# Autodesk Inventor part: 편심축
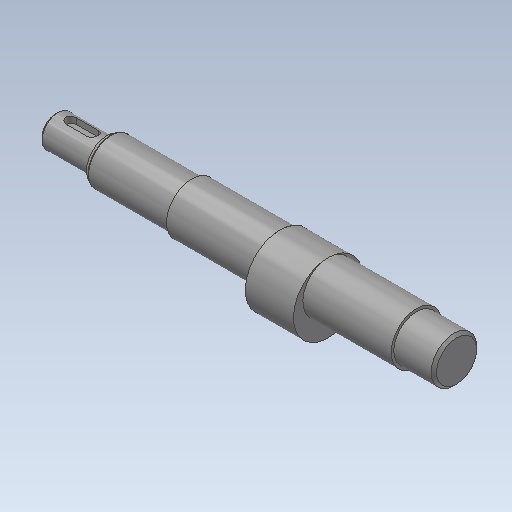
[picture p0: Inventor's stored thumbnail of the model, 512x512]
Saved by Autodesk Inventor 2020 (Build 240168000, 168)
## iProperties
Created: 2017-08
Part Number: 편심축
Material: 강철, 연강
Document SubType Name: Modeling
Designer: mduedu
Density: 1 g/cm^3
Appearance: 강철
Author: mduedu
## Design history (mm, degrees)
sketch "스케치1"
  geometry: L1 (0, 0)-(150, 0); L2 (150, 0)-(150, 8.5); L3 (150, 8.5)-(135, 8.5); L4 (135, 8.5)-(135, 9.5); L5 (135, 9.5)-(51, 9.5); L6 (51, 9.5)-(51, 8.5); L7 (51, 8.5)-(19, 8.5); L8 (19, 8.5)-(19, 6); L9 (19, 6)-(0, 6); L10 (0, 6)-(0, 0)
  constraints: 20 end point, 6 parallel, 2 collinear, 2 perpendicular, 1 horizontal
  dimensions: "d0" = 150 distance of L1.start L1.end; "d1" = 17 diameter of L3 L1; "d2" = 19 diameter of L5 L1; "d3" = 12 diameter of L9 L1; "d4" = 19 distance of L8.end L9.end; "d5" = 15 distance of L2.end L3.end; "d6" = 84 distance of L4.end L5.end
revolve "회전1" sketch "스케치1" stored, may be unused: angle "d7" = 90 deg
node "작업 평면1"
sketch "스케치2"
  geometry: C1 r 9.5 at (0, 0) reference; C2 r 13 at (0, -3.5); 1 further point
  constraints: 1 centre point, 1 tangent, 1 vertical alignment
  dimensions: "d8" = 3.5 distance of point (0, 0) C2.centre
extrude "돌출1" join sketch "스케치2" stored distance "d9" = 18; taper "d10" = 0 deg
chamfer "모따기1" distance "d11" = 1; stored, may be unused: second distance "d12" = 2, angle "d13" = 45 deg
node "작업 평면2"
sketch "스케치3"
  geometry: L1 (3.5, -2)-(-4.5, -2); L2 (-4.5, -2)-(-4.5, 2); L3 (-4.5, 2)-(3.5, 2); L4 (3.5, 2)-(3.5, -2); L5 (9.5, 6)-(9.5, -6) reference; A1 r 2 centre (3.5, 0) between (3.5, -2) and (3.5, 2); A2 r 2 centre (-4.5, 0) between (-4.5, 2) and (-4.5, -2); A3 r 2 centre (3.5, 0) between (3.5, 2) and (3.5, -2); A4 r 2 centre (-4.5, 0) between (-4.5, -2) and (-4.5, 2); 1 further point
  constraints: 8 end point, 8 point on circle, 4 centre point, 2 midpoint, 2 parallel, 1 horizontal, 1 horizontal alignment, 1 perpendicular
  dimensions: "d14" = 12 dimension on A2 A1; "d16" = 4 distance between parallel lines of L3 L1; "d17" = 4 distance edge to line of A1 L5
extrude "돌출2" cut sketch "스케치3" distance "d18" = 2.5; taper "d19" = 0 deg
chamfer "모따기2" distance "d20" = 1; stored, may be unused: second distance "d21" = 2, angle "d22" = 45 deg
chamfer "모따기3" distance "d23" = 1; stored, may be unused: second distance "d24" = 2, angle "d25" = 60 deg
fillet "모깎기1" dims "d26" = 0.5
hole "구멍1" diameter "d29" = 3.242; stored, may be unused: countersink angle "d33" = 90 deg, drill point angle "d35" = 118 deg; dims "d30" = 8, "d31" = 4, "d32" = 2, "d34" = 10, "d48" = 10, "d49" = 10
sketch "스케치4"
  geometry: L1 (13.5, -6)-(15, -4.5); L2 (15, -4.5)-(16.5, -6); L3 (15, -6)-(13.5, -6); L4 (15, -6)-(15, -4.5); L5 (1, -6)-(19, -6) reference; L6 (19, -6)-(19, 6) reference; 1 further point
  constraints: 8 end point, 1 collinear, 1 horizontal, 1 point on line, 1 vertical, 1 other
  dimensions: "d42" = 4 distance between parallel lines of L6 L4; "d43" = 3 distance of L1.start L2.end; "d44" = 90 deg angle of L1 L2
revolve "회전2" sketch "스케치4" stored, may be unused: angle "d45" = 90 deg
node "작업점1"
node "솔리드1"
node "절단 모서리 투영1"
other parameters: "d38" = -42
